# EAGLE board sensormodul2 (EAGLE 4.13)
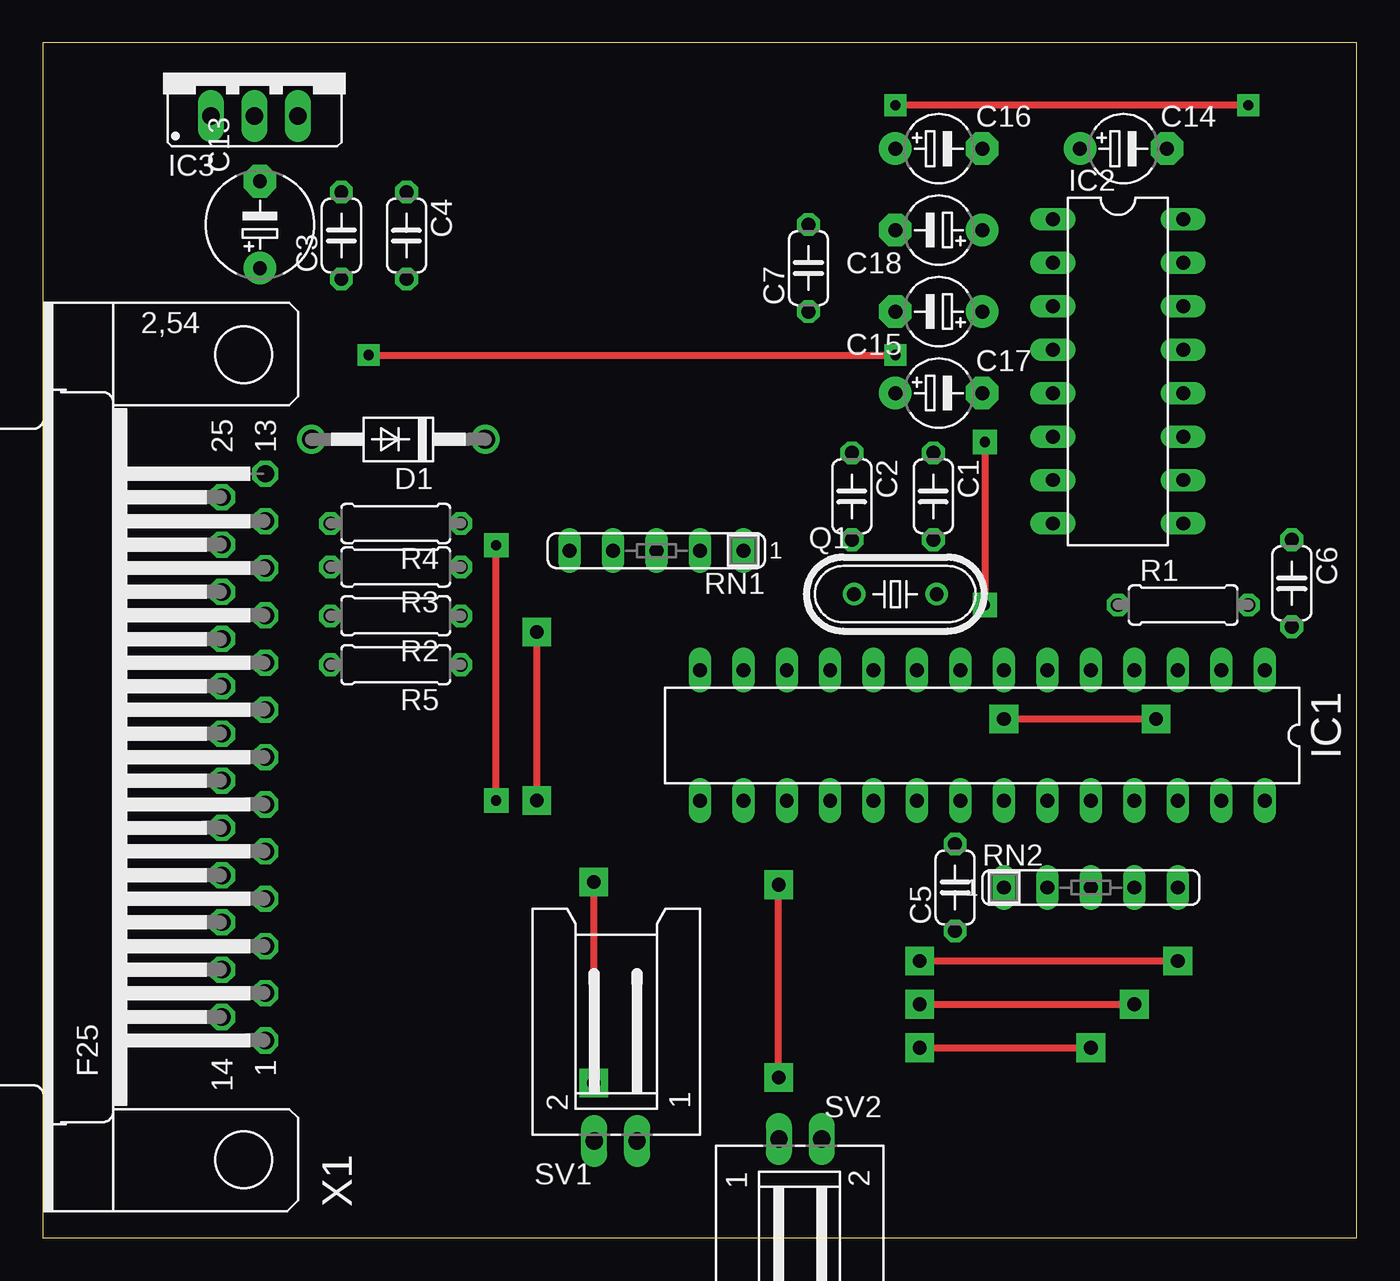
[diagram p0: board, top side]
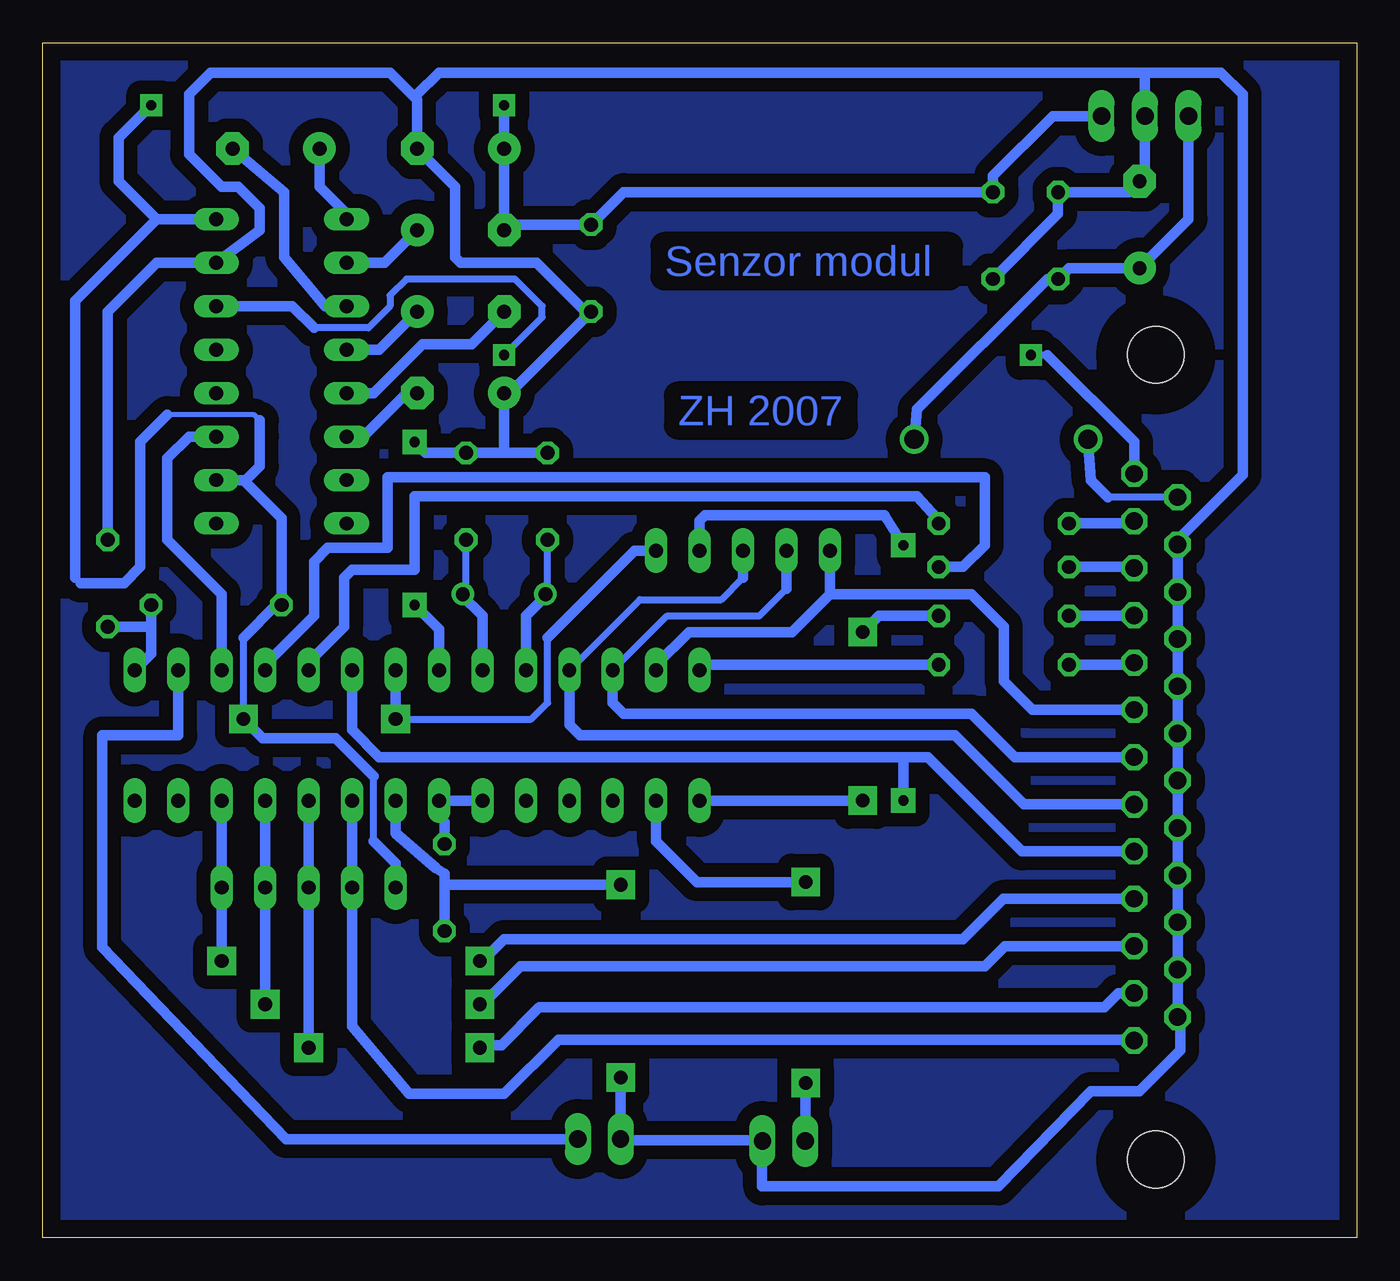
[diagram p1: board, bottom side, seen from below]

Size 76.81 x 69.84 mm. Coordinates in mm from the lower left corner, seen from the top.
Outline: 0,0 76.81,0 76.81,69.84 0,69.84 0,0
Copper layers (1*16): Top 0.035mm / dielectric 1.5mm / Bottom 0.035mm
Design rules "default": minimum track width 10mil, minimum drill 24mil, track to track 8mil, track to pad 8mil, pad to pad 8mil, via to via 8mil, smd to smd 8mil, copper to edge 40mil, drill to drill 8mil, minimum pad ring 10mil, minimum via ring 8mil, stop-mask expansion 4mil, vias tented up to drill 0mil, thermal gap 10mil

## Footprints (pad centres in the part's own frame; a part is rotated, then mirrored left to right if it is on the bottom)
C050-024X044 = drill 0.813 octagon: 1 -2.54,0; 2 2.54,0
E5-6 = drill 0.813 pad 1.905 round: + -2.54,0 | drill 0.813 pad 1.905 octagon: - 2.54,0
E5-4 = drill 0.813 pad 1.905 round: + -2.54,0 | drill 0.813 pad 1.905 octagon: - 2.54,0
DO41-10 = drill 1.118 round: A 5.08,0; C -5.08,0
DIL28-3 = drill 0.813 long: 1 -16.51,-3.81; 2 -13.97,-3.81; 3 -11.43,-3.81; 4 -8.89,-3.81; 5 -6.35,-3.81; 6 -3.81,-3.81; 7 -1.27,-3.81; 8 1.27,-3.81; 9 3.81,-3.81; 10 6.35,-3.81; 11 8.89,-3.81; 12 11.43,-3.81; 13 13.97,-3.81; 14 16.51,-3.81; 15 16.51,3.81; 16 13.97,3.81; 17 11.43,3.81; 18 8.89,3.81; 19 6.35,3.81; 20 3.81,3.81; 21 1.27,3.81; 22 -1.27,3.81; 23 -3.81,3.81; 24 -6.35,3.81; 25 -8.89,3.81; 26 -11.43,3.81; 27 -13.97,3.81; 28 -16.51,3.81
DIL16 = drill 0.813 long: 1 -8.89,-3.81; 2 -6.35,-3.81; 3 -3.81,-3.81; 4 -1.27,-3.81; 5 1.27,-3.81; 6 3.81,-3.81; 7 6.35,-3.81; 8 8.89,-3.81; 9 8.89,3.81; 10 6.35,3.81; 11 3.81,3.81; 12 1.27,3.81; 13 -1.27,3.81; 14 -3.81,3.81; 15 -6.35,3.81; 16 -8.89,3.81
78XXS = drill 1.016 long: GND 0,-2.54; IN -2.54,-2.54; OUT 2.54,-2.54
HC49/S = drill 0.813 round: 1 -2.413,0; 2 2.413,0
0207/7 = drill 0.813 octagon: 1 -3.81,0; 2 3.81,0
SIL5 = drill 0.813 long: 1 -5.08,0; 2 -2.54,0; 3 0,0; 4 2.54,0; 5 5.08,0
L02P = drill 1.016 long: 1 1.25,-6.25; 2 -1.25,-6.25
F25H = drill 1.016 octagon: 1 -16.561,-1.27; 2 -13.792,-1.27; 3 -11.049,-1.27; 4 -8.28,-1.27; 5 -5.512,-1.27; 6 -2.769,-1.27; 7 0,-1.27; 8 2.769,-1.27; 9 5.512,-1.27; 10 8.28,-1.27; 11 11.049,-1.27; 12 13.792,-1.27; 13 16.561,-1.27; 14 -15.189,1.27; 15 -12.421,1.27; 16 -9.652,1.27; 17 -6.909,1.27; 18 -4.14,1.27; 19 -1.372,1.27; 20 1.372,1.27; 21 4.14,1.27; 22 6.909,1.27; 23 9.652,1.27; 24 12.421,1.27; 25 15.189,1.27 | hole 3.302: -23.52,0; 23.52,0

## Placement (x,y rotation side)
C1  22pF  [C050-024X044]  52.06,43.33 270 top
C2  22pF  [C050-024X044]  47.3,43.33 270 top
C3  M1  [C050-024X044]  17.46,58.57 90 top
C4  M1  [C050-024X044]  21.27,58.57 270 top
C5  M1  [C050-024X044]  53.34,20.47 90 top
C6  M1  [C050-024X044]  73.02,38.25 270 top
C7  M1  [C050-024X044]  44.76,56.67 90 top
C13  100uF/25  [E5-6]  12.7,59.21 90 top
C14  [E5-4]  63.18,63.65 0 top
C15  [E5-4]  52.38,54.13 180 top
C16  [E5-4]  52.38,63.65 0 top
C17  [E5-4]  52.38,49.36 0 top
C18  [E5-4]  52.38,58.89 180 top
D1  1N4004  [DO41-10]  20.79,46.67 180 top
IC1  MEGA8-P  [DIL28-3]  54.92,29.36 180 top
IC2  MAX232  [DIL16]  62.86,50.63 270 top
IC3  7805  [78XXS]  12.38,68.1 0 top
Q1  [HC49/S]  49.84,37.62 0 top
R1  18k  [0207/7]  66.67,36.98 0 top
R2  [0207/7]  20.63,36.35 180 top
R3  [0207/7]  20.63,39.2 180 top
R4  [0207/7]  20.63,41.74 180 top
R5  [0207/7]  20.63,33.49 180 top
RN1  [SIL5]  35.87,40.16 180 top
RN2  [SIL5]  61.27,20.47 0 top
SV1  [L02P]  33.49,11.9 0 top
SV2  [L02P]  44.29,-0.48 180 top
X1  [F25H]  11.74,28.09 90 top

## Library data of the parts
C1-C7 C13-C18 R1-R5 = rcl
D1 = diode
IC1 = avr
IC2 = maxim
IC3 = v-reg
Q1 = crystal
RN1 RN2 = resistor-sil
SV1 SV2 = con-amp-mt
X1 = con-subd

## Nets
+5V: C4.1 C7.2 C16.+ C18.- IC1.7 IC2.10 IC2.16 IC3.OUT R1.1 RN1.1 RN2.1
GND: C1.1 C2.1 C3.2 C4.2 C5.1 C6.1 C7.1 C13.- C16.- C17.+ IC1.8 IC1.22 IC2.15 IC3.GND SV1.1 SV2.1 X1.14 X1.15 X1.16 X1.17 X1.18 X1.19 X1.20 X1.21 X1.22 X1.23 X1.24
N$1: C2.2 IC1.10 Q1.1
N$2: C1.2 IC1.9 Q1.2
N$3: C5.2 IC1.20 IC1.21
N$4: D1.A X1.25
N$5: C15.+ IC2.4
N$6: C14.+ IC2.1
N$7: C18.+ IC2.2
N$8: C17.- IC2.6
N$9: C14.- IC2.3
N$10: C15.- IC2.5
N$11: IC1.23 RN2.2 X1.1
N$12: IC1.24 RN2.3 X1.2
N$13: C3.1 C13.+ D1.C IC3.IN
N$14: IC1.25 RN2.4 X1.3
N$15: IC1.26 RN2.5 X1.4
N$16: IC1.6 RN1.2 X1.5
N$17: IC1.11 RN1.3 X1.6
N$18: C6.2 IC1.1 R1.2
N$19: IC1.14 R5.1
N$20: IC1.15 R2.1
N$21: IC1.4 R3.1
N$22: IC1.5 R4.1
N$23: IC1.12 RN1.4 X1.7
N$24: IC1.13 RN1.5 X1.8
N$25: R5.2 X1.9
N$26: R2.2 X1.10
N$27: R3.2 X1.11
N$28: R4.2 X1.12
N$29: IC1.3 IC2.11
N$30: IC2.14 X1.13
N$31: IC1.16 SV1.2
N$32: IC1.2 SV2.2

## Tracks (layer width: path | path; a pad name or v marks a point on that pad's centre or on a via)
+5V  (via drill 0.6 pad 1.27, 0.8 pad 1.68)
  Top 0.406: v70.48,66.19 v49.84,66.19 | v65.08,30.32 v56.19,30.32
  Bottom 0.305: 69.53,48.1 64.45,48.1 64.13,47.78
  Bottom 0.406: C18.- 49.52,59.21 | 74.61,38.25 74.92,38.57 | 63.18,36.98 R1.1 | v65.08,30.32 65.08,35.08 | IC1.7 v56.19,30.32 48.26,30.32 47.3,31.27 47.3,35.08 | 57.46,23.17 57.46,26.98
  Bottom 0.61: 49.52,59.21 C7.2 42.86,61.11 C4.1 21.27,62.06 17.77,65.56 IC3.OUT | 70.16,59.53 74.92,54.76 74.92,38.57 | 74.61,38.25 72.07,38.25 71.11,39.21 71.11,46.51 69.53,48.1 | 64.13,47.78 64.13,46.82 64.13,45.08 65,44.21 | C18.- C16.+ v49.84,66.19 | IC2.10 65.08,44.28 65,44.21 | 65,44.21 62.86,42.06 R1.1 | 70.16,59.53 IC2.16 | 70.16,59.53 72.39,61.75 72.39,64.29 v70.48,66.19 | 65.08,35.08 63.18,36.98 | RN2.1 56.19,21.9 57.46,23.17 | 57.46,26.98 59.69,29.2 63.97,29.2 v65.08,30.32 | v56.19,30.32 IC1.7 | 47.3,35.08 42.22,40.16 RN1.1 | 65,44.21
GND  (via drill 0.6 pad 1.42, 0.8 pad 1.68)
  Top 0.406: v43.02,9.36 v43.02,20.63 | v55.08,46.51 v55.08,36.98
  Bottom 0.406: 10.47,37.62 X1.23 | 10.47,35.08 X1.22 10.47,34.76 10.47,34.44 | X1.21 10.47,32.22 | X1.20 10.47,29.36 | X1.17 10.47,21.11 | X1.16 10.47,18.25 | X1.15 10.47,15.39 | 10.47,13.01 X1.14 10.47,12.85 10.63,12.85 10.47,13.01 | 12.38,62.06 C13.- 13.33,61.11 | X1.24 10.47,40.79 | 12.06,68.1 12.38,67.78 | 54.92,66.83 C16.- | 45.08,54.13 C7.1 | 49.52,49.36 C17.+ | 55.87,25.55 IC1.22 | 56.19,25.24 55.87,25.55 | C1.1 | 10.31,12.85 10.47,13.01 | 55.87,25.55 56.03,25.55 56.19,25.39
  Bottom 0.61: X1.23 X1.24 | 10.47,37.62 10.47,34.76 X1.21 X1.20 X1.19 X1.18 X1.17 X1.16 X1.15 10.47,13.01 | C6.1 73.02,54.13 70.16,56.98 IC2.15 64.13,58.89 64.13,60.16 65.4,61.43 66.35,61.43 68.26,63.34 68.26,66.83 66.99,68.1 56.51,68.1 54.92,66.51 C16.- 52.7,61.43 52.7,57.3 52.38,56.98 47.94,56.98 45.08,54.13 | 12.38,62.06 IC3.GND 12.38,67.78 | 13.33,61.11 C3.2 17.46,59.84 C4.2 | 10.47,40.79 6.66,44.6 6.66,66.83 7.93,68.1 12.06,68.1 53.65,68.1 54.92,66.83 | C7.1 49.52,49.36 | 53.34,20.63 C5.1 | 53.34,20.63 53.34,21.27 53.81,21.58 56.19,23.65 56.19,25.24 | 49.84,45.87 C2.1 | 49.84,45.87 C1.1 54.45,45.87 v55.08,46.51 | C17.+ 49.84,45.87 | v43.02,20.63 53.34,20.63 | 10.31,12.85 10.31,10.95 12.7,8.57 15.55,8.57 20.95,3.01 34.76,3.01 34.76,5.71 | v55.08,46.51 | IC1.8 53.65,35.55 v55.08,36.98 | 43.07,5.77 43.17,5.87 | SV2.1 43.07,5.77 | 43.07,5.77 43.02,5.71 | 34.76,5.71 34.86,5.61 | SV2.1 43.04,5.85 43.02,5.87 42.86,5.71 34.76,5.71 | 34.76,5.71 34.74,5.69 SV1.1 | v43.02,9.36 43.04,9.34 SV2.1
N$1
  Bottom 0.406: Q1.1 47.3,37.62 C2.2
  Bottom 0.61: IC1.10 48.57,36.35 47.3,37.62
N$2
  Bottom 0.406: 52.38,37.62 Q1.2 52.06,37.62 C1.2
  Bottom 0.61: IC1.9 51.11,36.35 52.38,37.62
N$3
  Bottom 0.406: 53.34,24.28 53.65,24.6
  Bottom 0.61: C5.2 53.34,24.28 | 53.65,24.6 IC1.21 IC1.20
N$4
  Bottom 0.406: X1.25 14.55,43.28
  Bottom 0.61: D1.A 15.55,44.28 14.55,43.28
N$5
  Bottom 0.61: IC2.4 57.15,51.9 C15.+
N$6
  Bottom 0.406: IC2.1 59.05,59.84
  Bottom 0.61: 59.05,59.84 60.64,61.43 C14.+
N$7
  Bottom 0.61: IC2.2 56.83,56.98 C18.+
N$8
  Bottom 0.61: C17.- 55.56,49.36 58.1,46.82 IC2.6
N$9
  Bottom 0.61: IC2.3 60.32,54.45 62.7,57.3 62.7,61.11 C14.-
N$10
  Bottom 0.61: IC2.5 57.46,49.36 54.6,52.22 51.75,52.22 C15.-
N$11
  Bottom 0.61: IC1.23 RN2.2 58.73,12.38 55.4,8.41 49.84,8.41 46.67,11.58 13.01,11.58 X1.1
N$12  (via drill 0.8 pad 1.68)
  Top 0.406: v51.27,11.11 v61.27,11.11 | v61.27,11.11
  Bottom 0.406: 47.6,13.51 47.86,13.41 47.78,13.49 | v51.27,11.11 | 51.11,11.26 v51.27,11.11
  Bottom 0.61: IC1.24 RN2.3 v61.27,11.11 | 47.86,13.41 50,11.26 51.11,11.26 | X1.2 13.95,14.3 14.76,13.49 47.78,13.49
N$13
  Bottom 0.406: C3.1 18.09,56.03 | D1.C 26.03,46.67
  Bottom 0.61: C3.1 16.82,56.67 C13.+ 9.84,59.53 IC3.IN | 18.09,56.03 25.71,48.41 D1.C
N$14  (via drill 0.8 pad 1.68)
  Top 0.406: v51.27,13.65 63.65,13.65 v63.81,13.65
  Bottom 0.406: 51.11,13.65 v51.27,13.65
  Bottom 0.61: IC1.25 RN2.4 v63.81,13.65 | X1.3 20.57,17.04 21.74,15.87 48.89,15.87 51.11,13.65
N$15  (via drill 0.8 pad 1.68)
  Top 0.406: v51.27,16.19 v66.35,16.19
  Bottom 0.406: RN2.5 66.19,20.47 66.35,20.31 | 51.11,16.19 v51.27,16.19
  Bottom 0.61: RN2.5 IC1.26 | X1.4 20.66,19.81 23.01,17.46 49.84,17.46 51.11,16.19 | v66.35,16.19 66.35,20.31
N$16  (via drill 0.6 pad 1.42)
  Top 0.406: v26.51,25.55 v26.51,40.47
  Bottom 0.406: RN1.2 38.41,40
  Bottom 0.61: IC1.6 58.73,29.68 57.15,28.09 26.51,28.09 | X1.5 19.57,22.58 25.08,28.09 26.51,28.09 | RN1.2 38.41,41.9 38.09,42.22 27.62,42.22 v26.51,40.47 | 26.51,28.09 v26.51,25.55
N$17
  Bottom 0.406: IC1.11 41.91,37.3 37.14,37.3 35.87,38.57 | 35.87,39.84 35.55,40.16
  Bottom 0.61: IC1.11 46.03,30 45.4,29.36 23.49,29.36 19.45,25.32 X1.6 | 35.55,40.16 RN1.3 | 35.87,38.57 35.87,39.84
N$18
  Bottom 0.61: 70.48,35.71 70.48,34.13 IC1.1 | 70.48,35.71 R1.2 | 70.48,35.71 C6.2
N$19
  Bottom 0.406: 38.09,33.49 IC1.14
  Bottom 0.61: R5.1 38.09,33.49
N$20  (via drill 0.8 pad 1.68)
  Top 0.406: v28.89,25.55 v28.89,35.39
  Bottom 0.61: R2.1 27.93,36.35 v28.89,35.39 | v28.89,25.55 IC1.15
N$21
  Bottom 0.406: 63.81,33.49 IC1.4 | 56.51,44.44 56.67,44.44
  Bottom 0.61: 63.81,33.49 60.95,36.35 60.95,39.52 60.16,40.32 56.67,40.32 56.67,44.44 | R3.1 23.01,39.21 21.74,40.47 21.74,44.44 56.51,44.44
N$22
  Bottom 0.406: 56.67,39.05 56.19,39.05 | 61.27,33.65 IC1.5 | R4.1 24.28,41.74
  Bottom 0.61: 61.27,33.65 59.21,35.71 59.21,38.57 58.73,39.05 56.67,39.05 55.08,39.05 55.08,43.33 25.71,43.33 24.28,41.74
N$23
  Bottom 0.406: 34.6,30.63 34.28,30.63 | IC1.12 40.32,36.35 34.92,36.35 33.33,37.93
  Bottom 0.61: IC1.12 43.49,31.27 42.86,30.63 34.6,30.63 22.54,30.63 20,28.09 X1.7 | 33.33,37.93 RN1.4
N$24
  Bottom 0.61: IC1.13 40.95,33.49 39.05,35.39 33.02,35.39 30.79,37.62 | X1.8 18.96,30.86 20.63,32.54 20.63,35.71 22.54,37.62 30.79,37.62 | 30.79,37.62 RN1.5
N$25
  Bottom 0.406: X1.9 13.01,33.49
  Bottom 0.61: 13.01,33.49 R5.2
N$26
  Bottom 0.406: X1.10 13.01,36.35
  Bottom 0.61: 13.01,36.35 R2.2
N$27
  Bottom 0.406: X1.11 13.01,39.21
  Bottom 0.61: 13.01,39.21 R3.2
N$28
  Bottom 0.406: 12.7,41.74 12.83,41.88 X1.12
  Bottom 0.61: 12.7,41.74 R4.2
N$29
  Bottom 0.61: IC1.3 66.35,37.62 69.53,40.79 69.53,45.56 68.26,46.82 IC2.11 66.35,46.82
N$30  (via drill 0.6 pad 1.27)
  Top 0.406: v19.05,51.59 v49.84,51.59
  Bottom 0.406: 60.95,53.18 57.78,53.18 56.51,54.45 56.51,55.08 55.56,56.03 49.21,56.03 47.62,54.45 47.62,53.81 v49.84,51.59 | 18.09,51.59 v19.05,51.59
  Bottom 0.61: IC2.14 62.23,54.45 60.95,53.18 | X1.13 13.01,46.51 18.09,51.59
N$31  (via drill 0.8 pad 1.68)
  Top 0.406: v32.22,9.04 v32.22,20.79
  Bottom 0.61: IC1.16 40.95,23.17 38.57,20.79 v32.22,20.79 | SV1.2 32.24,9.02 v32.22,9.04
N$32
  Bottom 0.61: SV2.2 62.6,5.77 73.34,16.98 73.34,29.36 68.89,29.36 IC1.2
N$33
  pour Bottom (isolate 0.813): 0.79,69.37 0.95,69.37 0.95,0.63 75.88,0.63 75.88,69.37 0.63,69.37

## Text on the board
Bottom: Senzor modul | ZH 2007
